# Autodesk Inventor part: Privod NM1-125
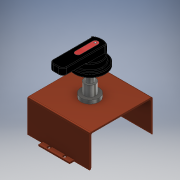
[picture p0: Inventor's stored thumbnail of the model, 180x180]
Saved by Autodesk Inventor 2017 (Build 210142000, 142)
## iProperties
Part Number: Privod NM1-125
Material: Типовые
Document SubType Name: Modeling
Designer: RSagdiev
Density: 1 g/cm^3
Appearance: По умолчанию
Author: RSagdiev
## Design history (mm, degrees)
sketch "Эскиз1"
  geometry: L1 (-22.5, 52)-(22.5, 52); L2 (22.5, 52)-(22.5, 43.5); L3 (22.5, 43.5)-(13.25, 43.5); L4 (-22.5, 43.5)-(-22.5, 52); L5 (0, 0)-(119.698, 0); L6 (0, 0)-(-104.809, 0); L7 (0, 94.88)-(0, -60.954); L8 (-13.25, 43.5)-(-9.25, 43.5); L9 (-9.25, 43.5)-(-9.25, 48.5); L10 (-11.25, 50.5)-(-11.25, 50.5); L11 (-13.25, 48.5)-(-13.25, 43.5); L12 (9.25, 43.5)-(9.25, 48.5); L13 (11.25, 50.5)-(11.25, 50.5); L14 (13.25, 43.5)-(9.25, 43.5); L15 (13.25, 48.5)-(13.25, 43.5); L16 (-13.25, 43.5)-(-22.5, 43.5); L17 (-9.25, 43.5)-(-13.25, 43.5); L18 (9.25, 43.5)-(-9.25, 43.5); L19 (13.25, 43.5)-(9.25, 43.5); A1 r 2 centre (-11.25, 48.5) between (-11.25, 50.5) and (-13.25, 48.5); A2 r 2 centre (-11.25, 48.5) between (-9.25, 48.5) and (-11.25, 50.5); A3 r 2 centre (11.25, 48.5) between (11.25, 50.5) and (9.25, 48.5); A4 r 2 centre (11.25, 48.5) between (13.25, 48.5) and (11.25, 50.5); 5 further points
  constraints: 38 end point, 10 point on line, 10 symmetric about line, 8 parallel, 8 point on circle, 4 centre point, 4 horizontal, 4 tangent, 2 perpendicular, 1 concentric, 1 midpoint, 1 vertical, 2 other
  dimensions: "d0" = 43.5 distance between parallel lines of L3 L6 (= 0.5 x Высота); "d1" = 8.5 distance of L1.end L2.end; "d2" = 45 distance between parallel lines of L2 L4 (= 0.5 x Ширина); "d3" = 4 distance of point (-13.25, 50.5) point (-9.25, 50.5); "d4" = 7 distance of point (-9.25, 50.5) L8.end; "d5" = 2 radius of A1 (derived); "d6" = 11.25 distance from line of L4 A1.centre (= 0.25 x d2)
extrude "Выдавливание1" new body sketch "Эскиз1" distance "d7" = 2; taper "d8" = 0 deg
mirror "Зеркальное отражение1"
sketch "Эскиз2"
  geometry: L1 (-22.5, 52)-(-22.5, 43.5) reference; L2 (22.5, 43.5)-(22.5, 52) reference; L3 (-22.5, -52)-(-22.5, -43.5) reference; L4 (22.5, -43.5)-(22.5, -52) reference; L5 (-45, 45.5)-(45, 45.5); L6 (45, 45.5)-(45, 43.5); L7 (45, 43.5)-(-45, 43.5); L8 (-45, 43.5)-(-45, 45.5); L9 (-22.5, 43.5)-(-13.25, 43.5) reference
  constraints: 8 end point, 2 parallel, 1 collinear, 1 horizontal, 1 perpendicular
  dimensions: "d13" = 90 distance of L5.start L5.end (= Ширина); "d14" = 2 distance of L5.end L6.end; "d15" = 22.5 distance between parallel lines of L1 L8 (= 0.25 x d13)
extrude "Выдавливание2" join sketch "Эскиз2" distance "d11" = 47 (computed from H1); taper "d12" = 0 deg
mirror "Зеркальное отражение2"
sketch "Эскиз3"
  geometry: L1 (-45, 45.5)-(-22.5, 45.5) reference; L2 (45, -45.5)-(-45, -45.5) reference; L3 (-45, 45.5)-(45, 45.5); L4 (45, 45.5)-(45, -45.5); L5 (45, -45.5)-(-45, -45.5); L6 (-45, -45.5)-(-45, 45.5); 1 further point
  constraints: 8 end point, 2 parallel, 1 horizontal, 1 perpendicular
extrude "Выдавливание3" join sketch "Эскиз3" distance "d16" = 2; taper "d17" = 0 deg
fillet "Сопряжение1" dims "d18" = 2
sketch "Эскиз4"
  geometry: L1 (45, -41.5)-(-45, -41.5) reference; L2 (45, -41.5)-(45, 41.5) reference; L3 (-45, 41.5)-(45, 41.5) reference; L4 (-45, 41.5)-(-45, -41.5) reference; L5 (-45, 41.5)-(-45, -41.5) reference; L6 (-45, -41.5)-(45, 41.5); L7 (45, -41.5)-(45, 41.5) reference; L8 (-45, 41.5)-(45, -41.5); C1 r 5 at (0, 0); 1 further point
  constraints: 4 end point, 1 centre point, 1 coincident
  dimensions: "d19" = 10 diameter of C1
extrude "Выдавливание4" cut sketch "Эскиз4" distance "d20" = 10; taper "d21" = 0 deg
sketch "Эскиз5"
  geometry: C1 r 5 at (0, 0) reference; C2 r 5 at (0, 0); C3 r 8 at (0, 0); 1 further point
  constraints: 2 centre point, 2 coincident
  dimensions: "d22" = 16 diameter of C3
extrude "Выдавливание5" new body sketch "Эскиз5" distance "d23" = 17 (= 0.333333 x H1); taper "d24" = 0 deg
sketch "Эскиз6"
  geometry: C1 r 5 at (0, 0) reference; C2 r 5 at (0, 0); 1 further point
  constraints: 1 centre point, 1 coincident
extrude "Выдавливание6" new body sketch "Эскиз6" distance "d25" = 67 (computed from H1); taper "d26" = 0 deg
sketch "Эскиз7"
  geometry: C1 r 5 at (0, 0) reference; C2 r 13 at (0, 0); C3 r 8 at (0, 0); C4 r 5 at (0, 0); 1 further point
  constraints: 3 centre point, 3 coincident
  dimensions: "d27" = 26 diameter of C2; "d28" = 16 diameter of C3; "d29" = 10 diameter of C4
extrude "Выдавливание7" new body sketch "Эскиз7" distance "d30" = 5; taper "d31" = 0 deg
extrude "Выдавливание8" join sketch "Эскиз7" distance "d32" = 20; taper "d33" = 0 deg
sketch "Эскиз8"
  geometry: C1 r 7 at (0, 0); 1 further point
  constraints: 1 centre point, 1 coincident
  dimensions: "d34" = 14 diameter of C1
extrude "Выдавливание9" new body sketch "Эскиз8" distance "d35" = 3; taper "d36" = 0 deg
fillet "Сопряжение2" dims "d37" = 3
sketch "Эскиз9"
  geometry: L1 (1, 13.17)-(-1, 13.17); L2 (-1, 13.17)-(-1, -13.17); L3 (-1, -13.17)-(1, -13.17); L4 (1, -13.17)-(1, 13.17); L5 (1, 13.17)-(-1, -13.17); L6 (-1, 13.17)-(1, -13.17); L7 (17.109, -1)-(-17.109, -1); L8 (-17.109, -1)-(-17.109, 1); L9 (-17.109, 1)-(17.109, 1); L10 (17.109, 1)-(17.109, -1); L11 (17.109, -1)-(-17.109, 1); L12 (-17.109, -1)-(17.109, 1); C1 r 4 at (0, 0) reference; C2 r 5 at (0, 0) reference; 1 further point
  constraints: 24 end point, 4 midpoint, 4 parallel, 2 horizontal, 2 perpendicular
  dimensions: "d38" = 2 distance of L3.end L2.end; "d39" = 2 distance of L7.end L8.end
extrude "Выдавливание10" cut sketch "Эскиз9" distance "d40" = 1; taper "d41" = 0 deg
sketch "Эскиз10"
  geometry: C1 r 17.5 at (0, 0); A1 r 4 centre (0, 0) between (1, -3.873) and (3.873, -1) reference; 1 further point
  constraints: 1 centre point, 1 coincident
  dimensions: "d42" = 35 diameter of C1
extrude "Выдавливание11" new body sketch "Эскиз10" distance "d43" = 6; taper "d44" = 0 deg; dims "d48" = 3, "d49" = 0
sketch "Эскиз11"
  geometry: C1 r 7 at (0, 0); C2 r 22.5 at (0, 0); 1 further point
  constraints: 2 centre point, 1 coincident
  dimensions: "d45" = 45 diameter of C2
extrude "Выдавливание12" join sketch "Эскиз11" distance "d46" = 6; taper "d47" = 0 deg
sketch "Эскиз12"
  geometry: L1 (-4, -49.361)-(4, -49.361); L2 (10, -43.361)-(10, 10.738); L3 (-10, 10.738)-(-10, -43.361); L4 (-10, -49.361)-(10, 14.361); L5 (10, -49.361)-(-10, 14.361); L6 (-12, 12.738)-(12, 12.738); A1 r 17.5 centre (0, 0) between (10, 14.361) and (0, -17.5) reference; A2 r 17.5 centre (0, 0) between (10, 14.361) and (0, -17.5) reference; A3 r 6 centre (-4, -43.361) between (-10, -43.361) and (-4, -49.361); A4 r 6 centre (4, -43.361) between (4, -49.361) and (10, -43.361); A5 r 2 centre (-12, 10.738) between (-10, 10.738) and (-12, 12.738); A6 r 2 centre (12, 10.738) between (12, 12.738) and (10, 10.738); A7 r 17.5 centre (0, 0) between (12, 12.738) and (-12, 12.738)
  constraints: 16 point on circle, 12 end point, 8 tangent, 6 point on line, 5 centre point, 2 equal radius, 2 horizontal, 2 midpoint, 1 coincident, 1 parallel, 1 perpendicular
  dimensions: "d63" = 20 distance of L4.end L5.end; "d64" = 6 radius of A3; "d66" = 10 distance from line of A1.centre L3; "d67" = 2 radius of A5; "d68" = 2 radius of A6 (derived)
extrude "Выдавливание13" join sketch "Эскиз12" distance "d55" = 10; taper "d56" = 0 deg
fillet "Сопряжение9" dims "d69" = 1
fillet "Сопряжение10" dims "d70" = 1
sketch "Эскиз13"
  geometry: L1 (0, 7.748)-(0, -17.5); L2 (-4, 7.748)-(-4, -17.5); L3 (4, -17.5)-(4, 7.748); A1 r 17.5 centre (0, 0) between (17.5, 0) and (0, -17.5) reference; A2 r 4 centre (0, 7.748) between (4, 7.748) and (-4, 7.748); A3 r 4 centre (0, -17.5) between (-4, -17.5) and (4, -17.5); 2 further points
  constraints: 8 end point, 5 point on circle, 4 tangent, 2 centre point, 1 midpoint, 1 parallel, 1 vertical
  dimensions: "d71" = 8 diameter of A3
extrude "Выдавливание14" cut sketch "Эскиз13" distance "d72" = 0.1; taper "d73" = 0 deg
sketch "Эскиз14"
  geometry: L1 (0, 9.652)-(1.649, 6.796); L2 (1.649, 6.796)-(-1.649, 6.796); L3 (-1.649, 6.796)-(0, 9.652); A1 r 4 centre (0, 7.748) between (4, 7.748) and (-4, 7.748) reference; 2 further points
  constraints: 6 end point, 1 coincident, 7 other
extrude "Выдавливание15" join sketch "Эскиз14" distance "d74" = 0.1; taper "d75" = 0 deg
node "Твердое тело1"
node "Спроецированная петля1"
node "Твердое тело2"
node "Твердое тело3"
node "Твердое тело4"
node "Твердое тело5"
node "Спроецированная петля2"
node "Твердое тело6"
node "Спроецированная петля3"
other parameters: "H1" = 51 [user parameter; used in 3 equation terms], "Высота" = 87 [user parameter; used in 1 equation term], "Ширина" = 90 [user parameter; used in 2 equation terms]
